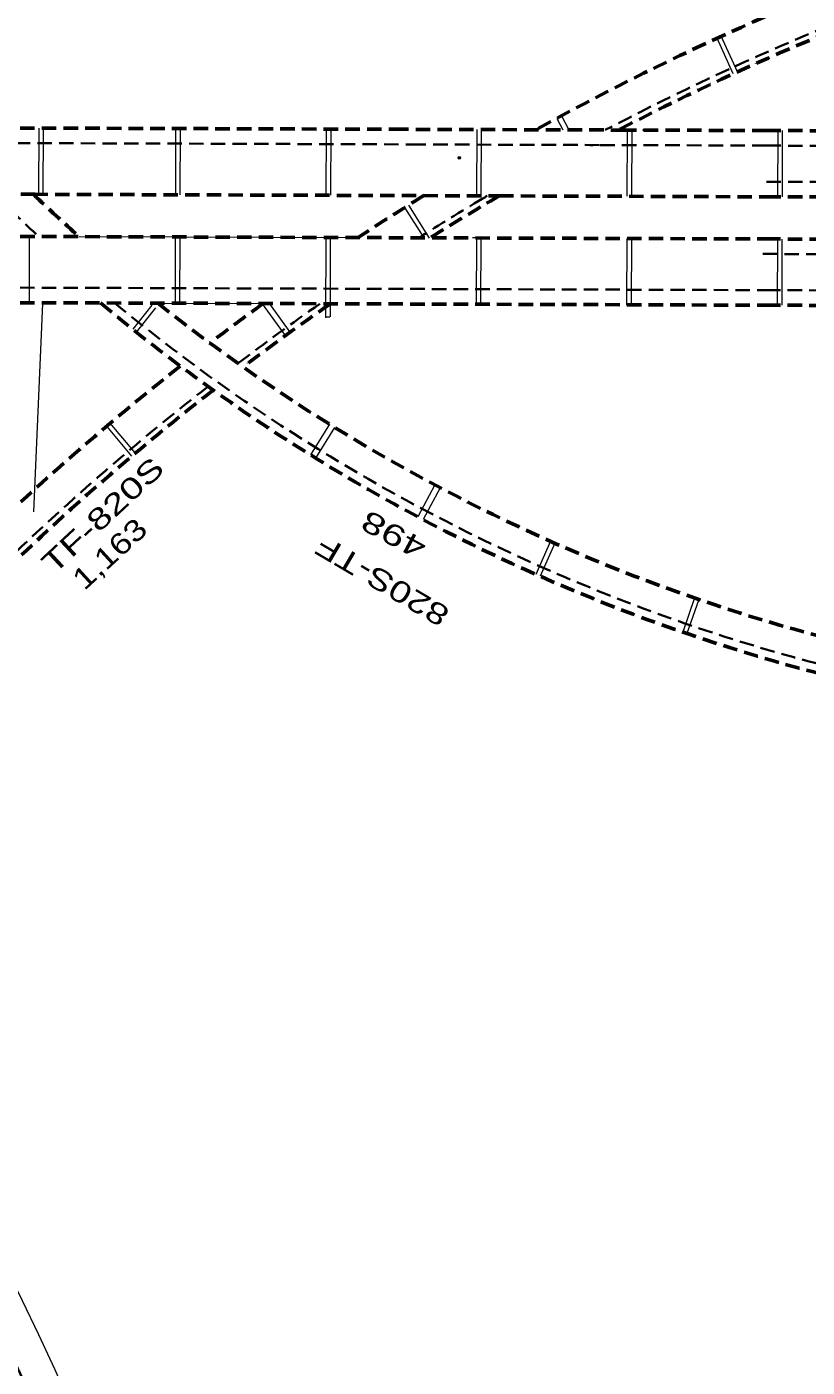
# Model space of a CAD drawing. Extents: x 2354993 to 2372084, y 6966390 to 6990057.
# Drawn here: x 2364756 to 2365274, y 6977227 to 6978118 of the extents above; entities that cross this region are included whole.
import ezdxf

# ---------------------------------------------------------------- set-up
doc = ezdxf.new("R2010")
doc.units = 0
doc.header["$LTSCALE"] = 3.2
doc.header["$PDMODE"] = 32
doc.header["$PDSIZE"] = 1.6
doc.linetypes.add('DASH_DOUBLE_DOT', pattern=[9.2, 5, -1.2, 0.3, -1.2, 0.3, -1.2])
doc.linetypes.add('MEDIUM_DASHED', pattern=[4.5, 3, -1.5])
for name, color, linetype, lineweight in [('12', 7, 'Continuous', 13), ('13', 7, 'Continuous', 13), ('17', 7, 'Continuous', 13), ('5', 7, 'Continuous', 35), ('60', 7, 'DASH_DOUBLE_DOT', 53), ('61', 7, 'Continuous', 13), ('9', 7, 'Continuous', 13)]:
    doc.layers.add(name, color=color, linetype=linetype, lineweight=lineweight)

msp = doc.modelspace()

# ---------------------------------------------------------------- linework, layer by layer
at = {"layer": '12'}
for p, q in [((2365224.948, 6978086.442), (2365214.15, 6978110.095)), ((2365227.675, 6978087.69), (2365216.877, 6978111.343)), ((2364763.481, 6978050.405), (2364763.332, 6978006.404)), ((2364766.481, 6978050.395), (2364766.332, 6978006.394)), ((2364854.481, 6978050.098), (2364854.333, 6978006.098)), ((2364857.481, 6978050.088), (2364857.332, 6978006.088)), ((2364954.481, 6978049.761), (2364954.333, 6978005.76)), ((2364957.48, 6978049.751), (2364954.481, 6978049.761)), ((2364957.48, 6978049.751), (2364957.332, 6978005.75)), ((2365054.48, 6978049.423), (2365054.331, 6978005.423)), ((2365057.479, 6978049.413), (2365057.331, 6978005.413)), ((2365154.48, 6978049.086), (2365154.331, 6978005.086)), ((2365157.479, 6978049.076), (2365154.48, 6978049.086)), ((2365157.479, 6978049.076), (2365157.33, 6978005.075)), ((2365254.479, 6978048.749), (2365254.331, 6978004.748)), ((2365257.479, 6978048.738), (2365257.33, 6978004.738)), ((2365054.331, 6978005.423), (2365057.331, 6978005.413)), ((2365019.476, 6977977.542), (2365006.781, 6977997.723)), ((2365023.164, 6977977.315), (2365009.318, 6977999.322)), ((2364757.238, 6977978.428), (2364757.089, 6977934.428)), ((2364854.238, 6977978.101), (2364854.09, 6977934.101)), ((2364857.238, 6977978.09), (2364857.089, 6977934.091)), ((2364954.238, 6977977.763), (2364954.058, 6977924.339)), ((2364957.237, 6977977.753), (2364957.06, 6977925.03)), ((2365054.237, 6977977.426), (2365051.735, 6977977.435)), ((2365054.237, 6977977.426), (2365054.088, 6977933.426)), ((2365057.236, 6977977.415), (2365057.088, 6977933.416)), ((2365154.237, 6977977.088), (2365154.088, 6977933.089)), ((2365157.236, 6977977.078), (2365157.087, 6977933.079)), ((2365254.236, 6977976.751), (2365254.088, 6977932.751)), ((2365257.236, 6977976.741), (2365257.087, 6977932.741)), ((2364838.733, 6977932.806), (2364825.939, 6977916.818)), ((2365157.087, 6977933.079), (2365154.088, 6977933.089)), ((2364841.075, 6977930.932), (2364828.285, 6977914.949)), ((2364953.961, 6977925.006), (2364956.96, 6977924.995)), ((2364825.415, 6977832.58), (2364808.656, 6977852.46)), ((2364827.706, 6977834.516), (2364810.949, 6977854.396)), ((2365103.591, 6977775.967), (2365093.851, 6977754.032)), ((2365106.334, 6977774.753), (2365096.595, 6977752.818)), ((2365199.176, 6977738.333), (2365191.349, 6977715.645)), ((2365202.013, 6977737.358), (2365194.186, 6977714.67))]:
    msp.add_line(p, q, dxfattribs=at)
msp.add_point((2364957.48, 6978049.751), dxfattribs=at)
at = {"layer": '17'}
for p, q in [((2364927.405, 6977912.554), (2364912.106, 6977933.737)), ((2364930.648, 6977914.896), (2364917.092, 6977933.665)), ((2364956.706, 6977853.748), (2364944.036, 6977833.365)), ((2364960.103, 6977851.636), (2364947.433, 6977831.254)), ((2365026.703, 6977813.423), (2365015.363, 6977792.279)), ((2365030.228, 6977811.532), (2365018.897, 6977790.405))]:
    msp.add_line(p, q, dxfattribs=at)
at = {"layer": '5', "linetype": 'MEDIUM_DASHED', "lineweight": 53}
for p, q in [((2365005.606, 6978049.588), (2364716.185, 6978050.564)), ((2365153.242, 6978049.09), (2365005.606, 6978049.589)), ((2365247.018, 6978048.774), (2365148.511, 6978049.107)), ((2365247.019, 6978048.774), (2365605.169, 6978047.567)), ((2364089.244, 6978008.678), (2364762.775, 6978006.406)), ((2364759.969, 6978006.415), (2365074.373, 6978005.355)), ((2365069.334, 6978005.372), (2365246.869, 6978004.773)), ((2365246.87, 6978004.774), (2365605.02, 6978003.566)), ((2363786.467, 6977981.699), (2365246.775, 6977976.776)), ((2365246.776, 6977976.776), (2365604.926, 6977975.568)), ((2363786.319, 6977937.7), (2365246.626, 6977932.776)), ((2365246.627, 6977932.775), (2365604.777, 6977931.568))]:
    msp.add_line(p, q, dxfattribs=at)
at = {"layer": '5', "lineweight": 13}
for p, q in [((2364756.304, 6978050.429), (2364756.349, 6978051.459)), ((2364790.346, 6977978.316), (2364975.778, 6977977.691)), ((2364760.235, 6977795.517), (2364766.247, 6977933.796)), ((2364842.712, 6977934.139), (2364912.564, 6977933.904))]:
    msp.add_line(p, q, dxfattribs=at)
at = {"layer": '5', "linetype": 'MEDIUM_DASHED'}
for p, q in [((2365017.01, 6978039.548), (2364725.744, 6978040.53)), ((2365135.994, 6978039.149), (2365017.009, 6978039.549)), ((2365246.983, 6978038.773), (2365129.646, 6978039.169)), ((2363786.352, 6977947.7), (2365246.66, 6977942.776)), ((2365246.661, 6977942.775), (2365604.811, 6977941.567))]:
    msp.add_line(p, q, dxfattribs=at)
for points in [[(2365246.984, 6978038.773), (2365605.134, 6978037.566), (2365605.134, 6978037.566)], [(2365246.903, 6978014.774), (2365605.053, 6978013.566), (2365605.053, 6978013.566)], [(2365244.474, 6977966.825), (2365602.624, 6977965.617), (2365602.624, 6977965.616)]]:
    msp.add_lwpolyline(points, dxfattribs=at)
at = {"layer": '5', "linetype": 'MEDIUM_DASHED', "lineweight": 53}
for centre, radius, start, end in [((2365952.337, 6976500.333), 1770.947, 100.46125, 118.99651), ((2365952.338, 6976500.332), 1744.947, 99.58224, 117.42976), ((2365591.415, 6978874.774), 1202.227, 226.24403, 228.21631), ((2365952.337, 6976500.333), 1770.947, 121.79432, 123.46547), ((2366144.618, 6976183.844), 2115.231, 120.55421, 122.00678), ((2365591.415, 6978874.774), 1226.227, 230.08464, 288.43495), ((2365591.415, 6978874.774), 1202.227, 231.48183, 288.43495), ((2365952.337, 6976500.333), 1770.947, 125.95357, 127.37676), ((2365952.338, 6976500.332), 1744.947, 124.76791, 127.11835), ((2365952.337, 6976500.333), 1770.947, 128.18302, 142.02993), ((2365952.338, 6976500.332), 1744.947, 127.94306, 142.26149), ((2366864.416, 6975944.503), 1927.859, 114.19653, 168.16581), ((2366864.416, 6975944.503), 1901.859, 114.19652, 168.16581)]:
    msp.add_arc(centre, radius, start, end, dxfattribs=at)
at = {"layer": '5', "linetype": 'MEDIUM_DASHED'}
for centre, radius, start, end in [((2365952.338, 6976500.332), 1748.947, 99.58224, 117.67913), ((2365591.415, 6978874.774), 1220.227, 225.36243, 227.27274), ((2365952.338, 6976500.332), 1748.947, 120.75073, 122.36718), ((2365591.415, 6978874.774), 1220.227, 230.42494, 288.43495), ((2365952.338, 6976500.332), 1748.947, 124.95489, 127.16), ((2365952.338, 6976500.332), 1748.947, 127.98178, 142.22456), ((2366864.416, 6975944.503), 1923.859, 114.19652, 168.16581)]:
    msp.add_arc(centre, radius, start, end, dxfattribs=at)
at = {"layer": '5'}
for centre, radius, start, end in [((2365952.338, 6976500.332), 1748.947, 120.62099, 120.75073), ((2363030.028, 6976428.641), 1895.859, 350.16881, 38.12295)]:
    msp.add_arc(centre, radius, start, end, dxfattribs=at)
at = {"layer": '5', "lineweight": 13}
for centre, radius, start, end in [((2365952.338, 6976500.332), 1744.947, 120.40007, 120.70834), ((2363030.028, 6976428.641), 1917.859, 350.16881, 38.12295), ((2363030.028, 6976428.641), 1891.859, 350.16881, 38.12295)]:
    msp.add_arc(centre, radius, start, end, dxfattribs=at)
at = {"layer": '60'}
msp.add_arc((2366864.416, 6975944.503), 1881.859, 114.65077, 155.69784, dxfattribs=at)
at = {"layer": '61'}
for p, q in [((2365107.638, 6978056.848), (2365111.791, 6978049.194)), ((2365110.714, 6978058.517), (2365115.727, 6978049.28))]:
    msp.add_line(p, q, dxfattribs=at)
at = {"layer": '9'}
for p in [(2365165.912, 6978049.048), (2365042.914, 6978030.655)]:
    msp.add_point(p, dxfattribs=at)

# ---------------------------------------------------------------- texts
at = {"layer": '13'}
for s, rotation, width, p in [('TF-820S', 43.001, 1.4, (2364773.513, 6977753.412)), ('1,163', 42.562, 1.25, (2364793.797, 6977742.775)), ('498', 151.573, 1.45, (2365022.526, 6977775.602)), ('820S-TF', 149.453, 1.35, (2365037.607, 6977730.626))]:
    msp.add_text(s, height=14, rotation=rotation, dxfattribs=dict(at, width=width)).set_placement(p)

doc.saveas('drawing.dxf')
